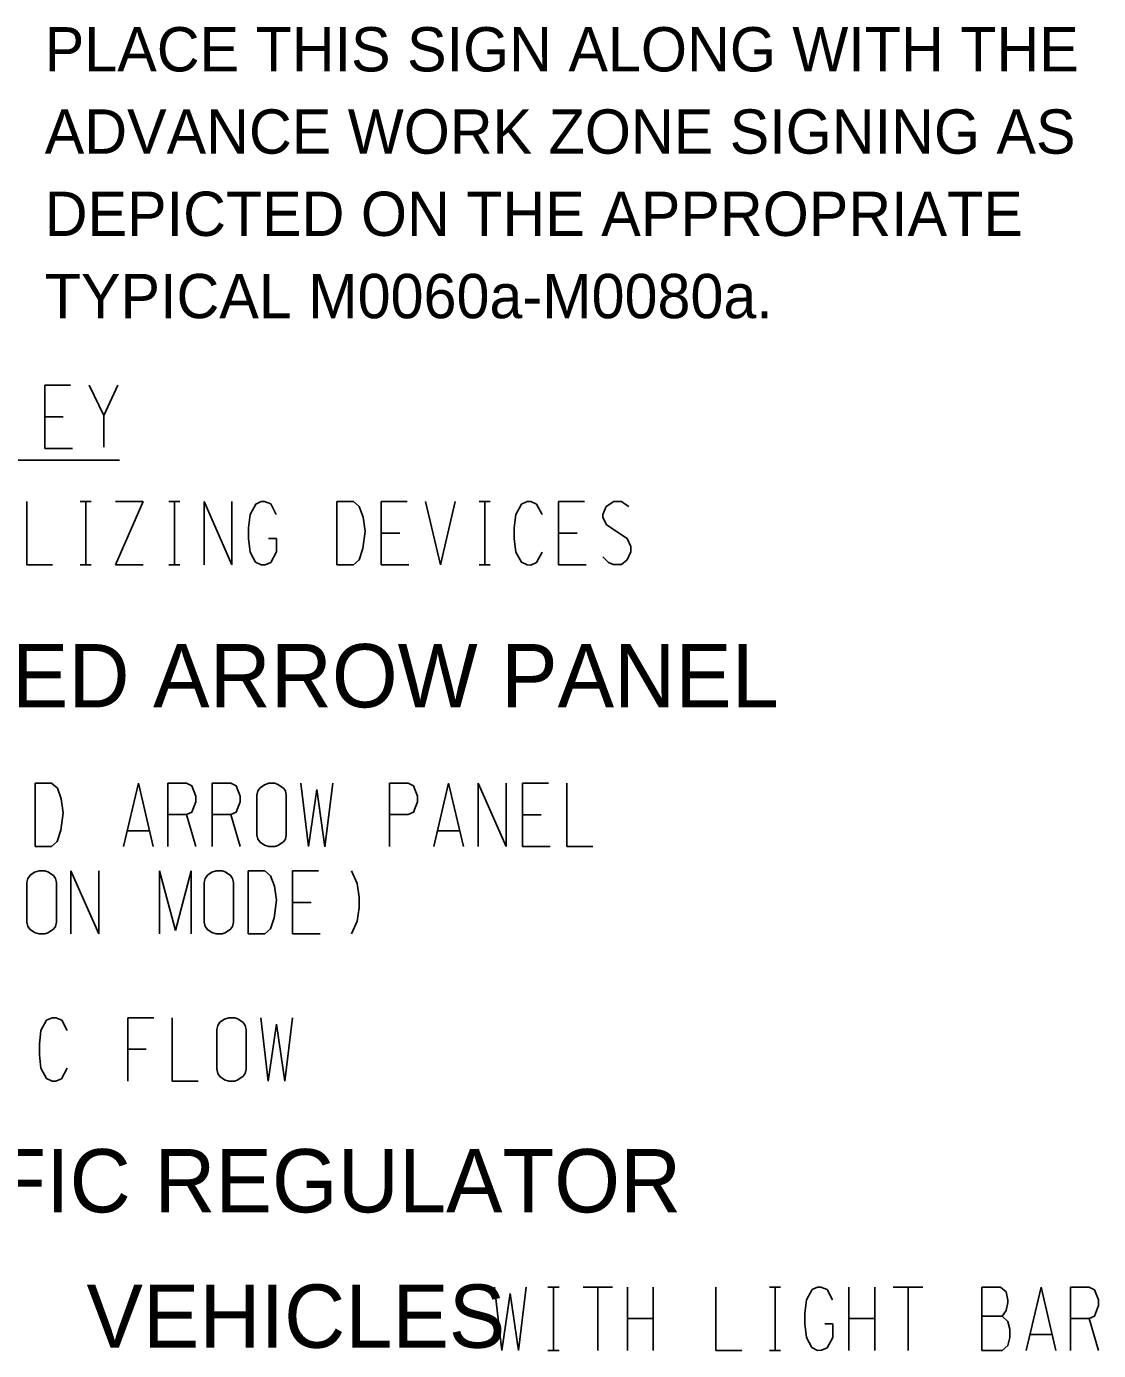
# Model space of a CAD drawing. Extents: x -1809 to 1557, y -1087 to 44.
# Drawn here: x -1215.7 to -1046.4, y -165.5 to 43.8 of the extents above; entities that cross this region are included whole.
import ezdxf

# ---------------------------------------------------------------- set-up
doc = ezdxf.new("R2010")
doc.units = 0
doc.layers.add('TRAFFIC_SIGNS_PR', color=7, linetype='Continuous')
doc.layers.add('TYPICAL_TEXT_DIMEN_EX', color=7, linetype='Continuous')

msp = doc.modelspace()

# ---------------------------------------------------------------- linework, layer by layer
at = {"layer": 'TYPICAL_TEXT_DIMEN_EX'}
for p, q in [((-1221.19, -24.73), (-1201.01, -24.73)), ((-1141.82, -155.43), (-1140.65, -165.43)), ((-1140.65, -165.43), (-1139.33, -156.43)), ((-1139.33, -156.43), (-1138.03, -165.45)), ((-1138.03, -165.45), (-1136.81, -155.43)), ((-1133.36, -155.43), (-1131.61, -155.43)), ((-1132.49, -155.43), (-1132.49, -165.43)), ((-1127.82, -155.43), (-1123.15, -155.43)), ((-1125.49, -155.43), (-1125.49, -165.43)), ((-1120.82, -155.43), (-1120.82, -165.43)), ((-1116.74, -165.43), (-1116.74, -155.43)), ((-1106.82, -155.43), (-1106.82, -165.43)), ((-1098.36, -155.43), (-1096.61, -155.43)), ((-1097.49, -155.43), (-1097.49, -165.43)), ((-1091.65, -155.82), (-1092.55, -157.46)), ((-1090.79, -155.43), (-1091.65, -155.82)), ((-1090.25, -155.43), (-1090.79, -155.43)), ((-1089.28, -155.79), (-1090.25, -155.43)), ((-1088.41, -157.46), (-1089.28, -155.79)), ((-1085.82, -155.43), (-1085.82, -165.43)), ((-1081.74, -165.43), (-1081.74, -155.43)), ((-1078.82, -155.43), (-1074.15, -155.43)), ((-1076.49, -155.43), (-1076.49, -165.43)), ((-1064.82, -155.43), (-1064.82, -165.43)), ((-1064.82, -155.43), (-1061.9, -155.43)), ((-1061.9, -155.43), (-1061.01, -156.18)), ((-1061.01, -156.18), (-1060.74, -157.48)), ((-1057.82, -165.43), (-1055.49, -155.43)), ((-1055.49, -155.43), (-1053.15, -165.43)), ((-1050.82, -165.43), (-1050.82, -155.43)), ((-1050.82, -155.43), (-1047.9, -155.43)), ((-1047.9, -155.43), (-1047.03, -155.84)), ((-1047.03, -155.84), (-1046.41, -157.46)), ((-1092.55, -157.46), (-1092.8, -159.57)), ((-1060.74, -157.85), (-1061.01, -159.12)), ((-1060.74, -157.48), (-1060.74, -157.85)), ((-1046.41, -158.34), (-1047.03, -160.01)), ((-1046.41, -157.46), (-1046.41, -158.34)), ((-1120.82, -160.37), (-1116.74, -160.37)), ((-1092.8, -159.57), (-1092.8, -161.23)), ((-1085.82, -160.37), (-1081.74, -160.37)), ((-1064.82, -160.01), (-1061.61, -160.01)), ((-1061.01, -159.12), (-1061.61, -160.01)), ((-1061.61, -160.01), (-1060.74, -160.87)), ((-1060.74, -160.87), (-1060.41, -162.09)), ((-1047.9, -160.37), (-1050.82, -160.37)), ((-1047.03, -160.01), (-1047.9, -160.37)), ((-1047.9, -160.37), (-1046.41, -165.43)), ((-1092.8, -161.23), (-1092.55, -163.39)), ((-1089.61, -161.26), (-1088.39, -161.26)), ((-1088.39, -161.26), (-1088.39, -163.37)), ((-1060.41, -162.09), (-1060.41, -163.37)), ((-1053.74, -162.93), (-1057.24, -162.93)), ((-1092.55, -163.39), (-1091.67, -164.98)), ((-1091.67, -164.98), (-1090.78, -165.43)), ((-1090.18, -165.42), (-1089.28, -165.04)), ((-1088.39, -163.37), (-1089.28, -165.04)), ((-1060.74, -164.67), (-1061.61, -165.43)), ((-1060.41, -163.37), (-1060.74, -164.67)), ((-1133.36, -165.43), (-1131.61, -165.43)), ((-1106.82, -165.43), (-1102.74, -165.43)), ((-1098.36, -165.43), (-1096.61, -165.43)), ((-1090.78, -165.43), (-1090.18, -165.42)), ((-1064.82, -165.43), (-1061.61, -165.43))]:
    msp.add_line(p, q, dxfattribs=at)
for points in [[(-1208.75, -12.89), (-1212.83, -12.89)], [(-1212.83, -12.89), (-1212.83, -22.89)], [(-1205.83, -12.89), (-1203.5, -17.68)], [(-1203.5, -17.68), (-1201.31, -12.89)], [(-1209.91, -17.89), (-1212.83, -17.89)], [(-1203.5, -22.68), (-1203.5, -17.6)], [(-1212.83, -22.89), (-1208.45, -22.89)], [(-1215.68, -31.3), (-1215.68, -41.3)], [(-1207.23, -31.3), (-1205.48, -31.3)], [(-1206.35, -31.3), (-1206.35, -41.3)], [(-1201.68, -31.3), (-1197.27, -31.3)], [(-1197.27, -31.3), (-1201.68, -41.3)], [(-1193.23, -31.3), (-1191.48, -31.3)], [(-1192.35, -31.3), (-1192.35, -41.3)], [(-1187.68, -41.3), (-1187.68, -31.3)], [(-1187.68, -31.3), (-1183.27, -41.3)], [(-1183.27, -41.3), (-1183.27, -31.3)], [(-1177.15, -31.66), (-1178.11, -31.3), (-1178.66, -31.3), (-1179.52, -31.69), (-1180.41, -33.33)], [(-1164.06, -31.3), (-1166.68, -31.3)], [(-1166.68, -31.3), (-1166.68, -41.3)], [(-1164.06, -31.3), (-1163.15, -32.08), (-1162.55, -33.74), (-1162.23, -35.96), (-1162.58, -38.72), (-1163.18, -40.49), (-1164.06, -41.3)], [(-1155.6, -31.3), (-1159.68, -31.3)], [(-1159.68, -31.3), (-1159.68, -41.3)], [(-1152.68, -31.3), (-1150.35, -41.3)], [(-1150.35, -41.3), (-1148.02, -31.3)], [(-1144.23, -31.3), (-1142.48, -31.3)], [(-1143.35, -31.3), (-1143.35, -41.3)], [(-1135.15, -31.69), (-1136.06, -31.3), (-1136.64, -31.3), (-1137.52, -31.69), (-1138.41, -33.33)], [(-1127.6, -31.3), (-1131.68, -31.3)], [(-1131.68, -31.3), (-1131.68, -41.3)], [(-1121.18, -31.69), (-1121.75, -31.3), (-1122.93, -31.3), (-1124.14, -32.08)], [(-1180.41, -33.33), (-1180.67, -35.44), (-1180.67, -37.11), (-1180.41, -39.27)], [(-1176.27, -33.33), (-1177.15, -31.66)], [(-1138.41, -33.33), (-1138.67, -35.46), (-1138.67, -37.13), (-1138.41, -39.27)], [(-1134.27, -33.33), (-1135.15, -31.69)], [(-1124.14, -32.08), (-1124.67, -33.33), (-1124.67, -33.75), (-1124.12, -34.99)], [(-1121.18, -31.69), (-1120.6, -32.08)], [(-1124.12, -34.99), (-1120.87, -37.13)], [(-1177.48, -37.13), (-1176.25, -37.13)], [(-1176.25, -37.13), (-1176.25, -39.24)], [(-1156.77, -36.3), (-1159.68, -36.3)], [(-1128.77, -36.3), (-1131.68, -36.3)], [(-1120.87, -40.52), (-1120.28, -39.24), (-1120.29, -38.38), (-1120.87, -37.13)], [(-1180.41, -39.27), (-1179.54, -40.85), (-1178.64, -41.3), (-1178.04, -41.29), (-1177.15, -40.91)], [(-1176.25, -39.24), (-1177.15, -40.91)], [(-1138.41, -39.27), (-1137.52, -40.88), (-1136.64, -41.3), (-1136.04, -41.32), (-1135.17, -40.93)], [(-1134.27, -39.27), (-1135.17, -40.93)], [(-1215.68, -41.3), (-1211.6, -41.3)], [(-1207.23, -41.3), (-1205.48, -41.3)], [(-1201.68, -41.3), (-1197.27, -41.3)], [(-1193.23, -41.3), (-1191.48, -41.3)], [(-1166.68, -41.3), (-1164.06, -41.3)], [(-1159.68, -41.3), (-1155.31, -41.3)], [(-1144.23, -41.3), (-1142.48, -41.3)], [(-1131.68, -41.3), (-1127.31, -41.3)], [(-1124.68, -40.05), (-1123.79, -40.93)], [(-1123.79, -40.93), (-1123.06, -41.25), (-1121.77, -41.24), (-1120.87, -40.52)], [(-1211.75, -75.82), (-1214.37, -75.82)], [(-1214.37, -75.82), (-1214.37, -85.82)], [(-1211.75, -75.82), (-1210.83, -76.6), (-1210.23, -78.27), (-1209.92, -80.48), (-1210.27, -83.24), (-1210.87, -85.01), (-1211.75, -85.82)], [(-1200.37, -85.82), (-1198.04, -75.82)], [(-1198.04, -75.82), (-1195.7, -85.82)], [(-1193.37, -85.82), (-1193.37, -75.82)], [(-1193.37, -75.82), (-1190.45, -75.82)], [(-1190.45, -75.82), (-1189.58, -76.24), (-1188.96, -77.85), (-1188.96, -78.74), (-1189.58, -80.4), (-1190.45, -80.77)], [(-1186.37, -85.82), (-1186.37, -75.82)], [(-1186.37, -75.82), (-1183.45, -75.82)], [(-1183.45, -75.82), (-1182.58, -76.24), (-1181.96, -77.85), (-1181.96, -78.74), (-1182.58, -80.4), (-1183.45, -80.77)], [(-1179.34, -77.7), (-1179.19, -77.02), (-1178.83, -76.52), (-1178.11, -76.04), (-1177.42, -75.82), (-1176.48, -75.82), (-1176.02, -76), (-1175.14, -76.57), (-1174.83, -77.02), (-1174.68, -77.7)], [(-1172.37, -75.82), (-1171.2, -85.82)], [(-1171.2, -85.82), (-1169.88, -76.82)], [(-1169.88, -76.82), (-1168.58, -85.85)], [(-1168.58, -85.85), (-1167.36, -75.82)], [(-1158.37, -85.82), (-1158.37, -75.82)], [(-1158.37, -75.82), (-1155.45, -75.82)], [(-1155.45, -75.82), (-1154.58, -76.24), (-1153.96, -77.85), (-1153.96, -78.74), (-1154.58, -80.4), (-1155.45, -80.77)], [(-1151.37, -85.82), (-1149.04, -75.82)], [(-1149.04, -75.82), (-1146.7, -85.82)], [(-1144.37, -85.82), (-1144.37, -75.82)], [(-1144.37, -75.82), (-1139.96, -85.82)], [(-1139.96, -85.82), (-1139.96, -75.82)], [(-1133.29, -75.82), (-1137.37, -75.82)], [(-1137.37, -75.82), (-1137.37, -85.82)], [(-1130.37, -75.82), (-1130.37, -85.82)], [(-1179.34, -83.95), (-1179.34, -77.7)], [(-1174.68, -83.95), (-1174.68, -77.7)], [(-1190.45, -80.77), (-1193.37, -80.77)], [(-1190.45, -80.77), (-1188.96, -85.82)], [(-1183.45, -80.77), (-1186.37, -80.77)], [(-1183.45, -80.77), (-1181.96, -85.82)], [(-1155.45, -80.77), (-1158.37, -80.77)], [(-1134.45, -80.82), (-1137.37, -80.82)], [(-1196.29, -83.32), (-1199.79, -83.32)], [(-1147.29, -83.32), (-1150.79, -83.32)], [(-1179.34, -83.95), (-1179.19, -84.62), (-1178.83, -85.12), (-1178.11, -85.6), (-1177.42, -85.82), (-1176.48, -85.82), (-1176.02, -85.65), (-1175.14, -85.07), (-1174.83, -84.62), (-1174.68, -83.95)], [(-1214.37, -85.82), (-1211.75, -85.82)], [(-1137.37, -85.82), (-1133, -85.82)], [(-1130.37, -85.82), (-1126.29, -85.82)], [(-1215.67, -91.51), (-1215.51, -90.84), (-1215.15, -90.34), (-1214.43, -89.86), (-1213.74, -89.63), (-1212.81, -89.63), (-1212.35, -89.81), (-1211.47, -90.38), (-1211.16, -90.84), (-1211, -91.51)], [(-1208.7, -99.63), (-1208.7, -89.63)], [(-1208.7, -89.63), (-1204.28, -99.63)], [(-1204.28, -99.63), (-1204.28, -89.63)], [(-1194.7, -99.63), (-1194.7, -89.63)], [(-1194.7, -89.63), (-1192.18, -99.08)], [(-1192.18, -99.08), (-1189.7, -89.63)], [(-1189.7, -89.63), (-1189.69, -99.63)], [(-1187.67, -91.51), (-1187.51, -90.84), (-1187.15, -90.34), (-1186.43, -89.86), (-1185.74, -89.63), (-1184.81, -89.63), (-1184.35, -89.81), (-1183.47, -90.38), (-1183.16, -90.84), (-1183, -91.51)], [(-1178.07, -89.63), (-1180.7, -89.63)], [(-1180.7, -89.63), (-1180.7, -99.63)], [(-1178.07, -89.63), (-1177.16, -90.42), (-1176.56, -92.08), (-1176.24, -94.29), (-1176.59, -97.06), (-1177.2, -98.83), (-1178.07, -99.63)], [(-1169.61, -89.63), (-1173.7, -89.63)], [(-1173.7, -89.63), (-1173.7, -99.63)], [(-1164.36, -89.64), (-1163.47, -91.67), (-1163.2, -93.8), (-1163.2, -95.47), (-1163.47, -97.6), (-1164.36, -99.63)], [(-1215.67, -97.76), (-1215.67, -91.51)], [(-1211, -97.76), (-1211, -91.51)], [(-1187.67, -97.76), (-1187.67, -91.51)], [(-1183, -97.76), (-1183, -91.51)], [(-1170.78, -94.63), (-1173.7, -94.63)], [(-1215.67, -97.76), (-1215.51, -98.43), (-1215.15, -98.93), (-1214.43, -99.41), (-1213.74, -99.63), (-1212.81, -99.63), (-1212.35, -99.46), (-1211.47, -98.89), (-1211.16, -98.43), (-1211, -97.76)], [(-1187.67, -97.76), (-1187.51, -98.43), (-1187.15, -98.93), (-1186.43, -99.41), (-1185.74, -99.63), (-1184.81, -99.63), (-1184.35, -99.46), (-1183.47, -98.89), (-1183.16, -98.43), (-1183, -97.76)], [(-1180.7, -99.63), (-1178.07, -99.63)], [(-1173.7, -99.63), (-1169.32, -99.63)], [(-1210.16, -113.26), (-1211.08, -112.87), (-1211.66, -112.87), (-1212.54, -113.26), (-1213.43, -114.9)], [(-1195.62, -112.87), (-1199.7, -112.87)], [(-1199.7, -112.87), (-1199.7, -122.87)], [(-1192.7, -112.87), (-1192.7, -122.87)], [(-1185.67, -114.74), (-1185.52, -114.07), (-1185.16, -113.57), (-1184.44, -113.09), (-1183.75, -112.87), (-1182.81, -112.87), (-1182.35, -113.05), (-1181.47, -113.62), (-1181.16, -114.07), (-1181.01, -114.74)], [(-1178.7, -112.87), (-1177.54, -122.87)], [(-1174.91, -122.9), (-1173.69, -112.87)], [(-1213.43, -114.9), (-1213.68, -117.04), (-1213.68, -118.7), (-1213.43, -120.84)], [(-1209.29, -114.9), (-1210.16, -113.26)], [(-1185.67, -120.99), (-1185.67, -114.74)], [(-1181.01, -120.99), (-1181.01, -114.74)], [(-1177.54, -122.87), (-1176.21, -113.87)], [(-1176.21, -113.87), (-1174.91, -122.9)], [(-1199.7, -117.82), (-1196.8, -117.82)], [(-1213.43, -120.84), (-1212.54, -122.45), (-1211.66, -122.87), (-1211.06, -122.9), (-1210.18, -122.5)], [(-1209.29, -120.84), (-1210.18, -122.5)], [(-1185.67, -120.99), (-1185.52, -121.67), (-1185.16, -122.17), (-1184.44, -122.65), (-1183.75, -122.87), (-1182.81, -122.87), (-1182.35, -122.7), (-1181.47, -122.12), (-1181.16, -121.67), (-1181.01, -120.99)], [(-1192.7, -122.87), (-1188.62, -122.87)]]:
    msp.add_lwpolyline(points, dxfattribs=at)

# ---------------------------------------------------------------- texts
at = {"layer": 'TRAFFIC_SIGNS_PR'}
for s, p in [('PLACE THIS SIGN ALONG WITH THE', (-1212.83, 36.68)), ('ADVANCE WORK ZONE SIGNING AS', (-1212.83, 23.68)), ('DEPICTED ON THE APPROPRIATE', (-1212.83, 10.68)), ('TYPICAL M0060a-M0080a.', (-1212.83, -2.32))]:
    msp.add_text(s, height=7, dxfattribs=at).set_placement(p)
at = {"layer": 'TYPICAL_TEXT_DIMEN_EX'}
for s, p in [('LIGHTED ARROW PANEL', (-1257.39, -63.81)), ('TRAFFIC REGULATOR', (-1255.7, -143.62)), ('VEHICLES', (-1206.24, -165.02))]:
    msp.add_text(s, height=10, dxfattribs=at).set_placement(p)

doc.saveas('drawing.dxf')
